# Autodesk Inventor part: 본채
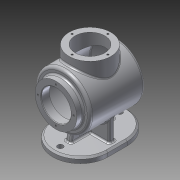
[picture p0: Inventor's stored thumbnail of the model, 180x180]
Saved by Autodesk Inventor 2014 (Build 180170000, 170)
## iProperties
Created: 2016-04
Part Number: 본채
Material: 알루미늄 6061
Document SubType Name: Modeling
Designer: basic
Density: 2.71 g/cm^3
Appearance: 알루미늄 - 평지
Mass: 909.819 g
Surface Area: 1227.74 cm^2
Volume: 335.726 cm^3
Author: basic
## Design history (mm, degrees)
sketch "스케치6"
  geometry: L1 (-50, -67.5)-(50, -67.5); L2 (50, -67.5)-(50, 67.5); L3 (50, 67.5)-(-50, 67.5); L4 (-50, 67.5)-(-50, -67.5); L5 (-50, -67.5)-(50, 67.5); 2 further points
  constraints: 10 end point, 2 parallel, 1 coincident, 1 horizontal, 1 midpoint, 1 perpendicular
  dimensions: "d31" = 100 distance of L2.end L3.end; "d32" = 135 distance of L3.end L1.start
extrude "돌출3" join sketch "스케치6" distance "d34" = 10; taper "d35" = 0 deg
fillet "모깎기1" dims "d36" = 50
chamfer "모따기2" distance "d37" = 3; stored, may be unused: second distance "d38" = 2, angle "d39" = 45 deg
sketch "스케치7"
  geometry: L1 (64.5, 10)-(67.5, 7) reference; L2 (67.5, 7)-(67.5, 0) reference; L3 (67.5, 0)-(-67.5, 0) reference; L4 (-67.5, 0)-(-67.5, 7) reference; L5 (-67.5, 7)-(-64.5, 10) reference; L6 (-64.5, 10)-(64.5, 10) reference; L7 (-62, 79)-(60, 79); L8 (-62, 79)-(-62, 117); L9 (-62, 117)-(-50, 117); L10 (-50, 117)-(-50, 129); L11 (-62, 106)-(-47, 106); L12 (-47, 106)-(-47, 126); L13 (-47, 126)-(47.145, 126); L14 (-50, 129)-(49.087, 129); A1 r 120 centre (60, 79) between (-50, 126.958) and (-60, 79); A2 r 120 centre (-60, 79) between (60, 79) and (49.087, 129); A3 r 117 centre (-60, 79) between (57, 79) and (47.145, 126); 1 further point
  constraints: 16 end point, 6 point on circle, 4 point on line, 3 centre point, 3 parallel, 3 perpendicular, 1 coincident, 1 horizontal, 1 midpoint
  dimensions: "d41" = 79 distance between parallel lines of L3 L7; "d44" = 240 diameter of A1; "d46" = 3 radial gap between concentric circles of A2 A3; "d47" = 15 distance of L11.start L11.end; "d48" = 12 distance of L8.end L9.end; "d49" = 3 distance between parallel lines of L13 L14; "d50" = 50 distance between parallel lines of L7 L14; "d51" = 38 distance between parallel lines of L7 L9; "d52" = 27 distance between parallel lines of L7 L11; "d115" = 62 distance from line of point (0, 0) L8; "d136" = 122 distance of L7.start L7.end
revolve "회전3" sketch "스케치7" stored, may be unused: angle "d53" = 90 deg
sketch "스케치8" dims "d54" = 65
  geometry: L1 (0, 0)-(32.5, 0); C1 r 38 at (0, 0) reference; 2 further points
  constraints: 2 coincident, 2 end point, 1 horizontal, 1 horizontal alignment, 2 other
hole "구멍1" sketch "스케치8" at (32.5, 0) diameter "d55" = 3.242; stored, may be unused: countersink angle "d59" = 90 deg, drill point angle "d61" = 118 deg; dims "d56" = 8, "d57" = 4, "d58" = 2, "d60" = 10
node "작업 평면1"
sketch "스케치12"
  geometry: C1 r 5 at (0, -54); C2 r 5 at (0, 54); A1 r 47 centre (0, -17.5) between (-47, -17.5) and (47, -17.5) reference; A2 r 47 centre (0, 17.5) between (47, 17.5) and (-47, 17.5) reference; 1 further point
  constraints: 2 centre point, 2 vertical alignment
  dimensions: "d83" = 10 diameter of C1; "d84" = 10 diameter of C2; "d85" = 54 distance of point (0, 0) C1.centre; "d86" = 54 distance of C2.centre point (0, 0)
extrude "돌출6" cut sketch "스케치12" stored distance "d87" = 10; taper "d88" = 0 deg
fillet "모깎기2" dims "d89" = 2
fillet "모깎기3" dims "d90" = 5
chamfer "모따기3" distance "d91" = 1; stored, may be unused: second distance "d92" = 2, angle "d93" = 45 deg
sketch "스케치14"
  geometry: L1 (-50, 7)-(-47, 10) reference; L2 (-47, 10)-(47, 10) reference; L3 (47, 10)-(50, 7) reference; L4 (50, 7)-(50, 0) reference; L5 (50, 0)-(-50, 0) reference; L6 (-50, 0)-(-50, 7) reference; L7 (40, 10)-(40, 49); L8 (-40, 49)-(-40, 10); C1 r 47 at (0, 79) reference; A1 r 50 centre (0, 79) between (-40, 49) and (40, 49) reference; 1 further point
  constraints: 4 end point, 2 point on circle, 2 point on line, 1 parallel
  dimensions: "d99" = 40 distance from line of C1.centre L7; "d100" = 80 distance between parallel lines of L8 L7
extrude "돌출8" join sketch "스케치14" stored distance "d101" = 10; taper "d102" = 0 deg
sketch "스케치15"
  geometry: L1 (-51.026, 111.5)-(-52, 113.121) reference; L2 (-52, 113.121)-(-62, 113.121) reference; L3 (-62, 113.121)-(-62, 117) reference; L4 (-62, 117)-(-50, 117) reference; L5 (-50, 117)-(-50, 124) reference; L6 (-45, 129)-(45.83, 129) reference; L7 (45.83, 126)-(-45, 126) reference; L8 (-47, 124)-(-47, 106) reference; L9 (-47, 106)-(-61, 106) reference; L10 (-61, 106)-(-62, 107) reference; L11 (-62, 107)-(-62, 109.879) reference; L12 (-62, 109.879)-(-52, 109.879) reference; L13 (-52, 109.879)-(-51.026, 111.5) reference; L14 (49, 10)-(49, 0) reference; L15 (49, 0)-(-49, 0) reference; L16 (-49, 0)-(-49, 10) reference; L17 (-49, 10)-(-5, 10) reference; L18 (-5, 10)-(-5, 29) reference; L19 (-5, 29)-(-45, 29) reference; L20 (-50, 34)-(-50, 41) reference; L21 (-50, 41)-(-62, 41) reference; L22 (-62, 41)-(-62, 44.879) reference; L23 (-62, 44.879)-(-52, 44.879) reference; L24 (-52, 44.879)-(-51.026, 46.5) reference; L25 (-51.026, 46.5)-(-52, 48.121) reference; L26 (-52, 48.121)-(-62, 48.121) reference; L27 (-62, 48.121)-(-62, 51) reference; L28 (-62, 51)-(-61, 52) reference; L29 (-61, 52)-(-47, 52) reference; L30 (-47, 52)-(-47, 34) reference; L31 (-45, 32)-(45.83, 32) reference; L32 (45.83, 29)-(5, 29) reference; L33 (5, 29)-(5, 10) reference; L34 (5, 10)-(49, 10) reference; L35 (-67.5, 7)-(-64.5, 10) reference; L36 (-64.5, 10)-(-59, 10) reference; L37 (-59, 10)-(-59, 0) reference; L38 (-59, 0)-(-67.5, 0) reference; L39 (-67.5, 0)-(-67.5, 7) reference; L40 (64.5, 10)-(67.5, 7) reference; L41 (67.5, 7)-(67.5, 0) reference; L42 (67.5, 0)-(59, 0) reference; L43 (59, 0)-(59, 10) reference; L44 (59, 10)-(64.5, 10) reference; L45 (-36.65, 29)-(-40, 10); A1 r 5 centre (-45, 124) between (-45, 129) and (-50, 124) reference; A2 r 2 centre (-45, 124) between (-45, 126) and (-47, 124) reference; A3 r 5 centre (-45, 34) between (-50, 34) and (-45, 29) reference; A4 r 2 centre (-45, 34) between (-47, 34) and (-45, 32) reference; A5 r 2 centre (45.83, 34) between (45.83, 32) and (47.671, 33.217) reference; A6 r 117 centre (-60, 79) between (47.671, 33.217) and (47.671, 124.783) reference; A7 r 2 centre (45.83, 124) between (47.671, 124.783) and (45.83, 126) reference; A8 r 5 centre (45.83, 124) between (50.431, 125.957) and (45.83, 129) reference; A9 r 120 centre (-60, 79) between (50.431, 32.043) and (50.431, 125.957) reference; A10 r 5 centre (45.83, 34) between (45.83, 29) and (50.431, 32.043) reference; 1 further point
  constraints: 2 end point, 2 point on line
  dimensions: "d105" = 40 horizontal distance of point (0, 0) L45.end; "d106" = 100 deg angle of L17 L45
feature "리브1" sketch "스케치15" dims "d107" = 1, "d108" = 10, "d109" = 0, "d110" = 0, "d111" = 1, "d112" = 1
sketch "스케치16"
  geometry: L1 (38, -62)-(-38, -62) reference; C1 r 38 at (0, 0); 1 further point
  constraints: 2 coincident, 1 centre point
  dimensions: "d113" = 76 diameter of C1
extrude "돌출9" join sketch "스케치16" stored distance "d116" = 10; taper "d117" = 0 deg
sketch "스케치17"
  geometry: C1 r 38 at (0, 0) reference; C2 r 27 at (0, 0)
  constraints: 1 centre point, 1 coincident
  dimensions: "d118" = 54 diameter of C2
extrude "돌출10" cut sketch "스케치17" stored distance "d119" = 10; taper "d120" = 0 deg
sketch "스케치18" dims "d121" = 65
  geometry: L1 (0, 0)-(-32.5, 0); C1 r 38 at (0, 0) reference; 1 further point
  constraints: 2 coincident, 2 end point, 1 horizontal, 1 horizontal alignment, 2 other
hole "구멍3" sketch "스케치18" at (-32.5, 0) diameter "d122" = 3.242; stored, may be unused: countersink angle "d126" = 90 deg, drill point angle "d128" = 118 deg; dims "d123" = 8, "d124" = 4, "d125" = 2, "d127" = 10
fillet "모깎기4" dims "d132" = 3
fillet "모깎기5" dims "d133" = 3
node "작업 평면3"
sketch "스케치19"
  geometry: L1 (26.339, -79)-(-26.339, -79) reference; L2 (-26.339, -79)-(-26.339, -72) reference; L3 (-20.069, -69)-(20.069, -69) reference; L4 (26.339, -72)-(26.339, -79) reference; 3 further points
  constraints: 1 coincident, 3 other
feature "엠보싱1" sketch "스케치19" dims "d31" = 100, "d32" = 135, "d41" = 79, "d44" = 240, "d46" = 3, "d47" = 15, "d48" = 12, "d49" = 3, "d50" = 50, "d51" = 38, "d52" = 27, "d115" = 62, "d134" = 0.5, "d135" = 0, "d136" = 122
node "솔리드2"
pattern_circular "원형 패턴1" dims angle "d63" = 360 deg
pattern_circular "원형 패턴3" dims angle "d130" = 360 deg
mirror "대칭1"
node "절단 모서리 투영2"
node "절단 모서리 투영4"
node "절단 모서리 투영5"
node "절단 모서리 투영6"
other parameters: "d65" = 144
